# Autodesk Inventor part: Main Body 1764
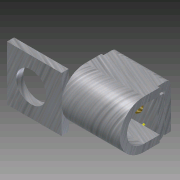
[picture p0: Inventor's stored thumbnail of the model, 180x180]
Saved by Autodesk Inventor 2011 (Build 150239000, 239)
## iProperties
Created: 2008-01
Part Number: Main Body 1764
Document SubType Name: Modeling
Designer: rlindsay
Density: 1 g/cm^3
Author: rlindsay
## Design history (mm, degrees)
sketch "Sketch1"
  geometry: L1 (-12.629, -4.841)-(0.071, -4.841); L2 (0.071, -4.841)-(0.071, -17.541); L3 (0.071, -17.541)-(-12.629, -17.541); L4 (-12.629, -17.541)-(-12.629, -4.841); C1 r 3.493 at (-6.978, -11.191)
  constraints: 8 end point, 2 parallel, 1 centre point, 1 horizontal, 1 perpendicular
  dimensions: "d0" = 6.985 diameter of C1; "d1" = 12.7 distance between parallel lines of L3 L1; "d2" = 6.35 distance from line of L3 C1.centre (= 0.5 x d1); "d3" = 12.7 distance of L1.start L1.end; "d5" = 7.0485 distance from line of L2 C1.centre (computed from d0)
extrude "Extrusion1" new body sketch "Sketch1" distance "d6" = 1.651; taper "d7" = 0 deg
sketch "Sketch2"
  geometry: L1 (-1.651, 12.7)-(-1.651, 0) reference; L2 (0, 0)-(-1.651, 0) reference; L3 (0, 12.7)-(0, 0) reference; L4 (0, 12.7)-(-1.651, 12.7) reference; L5 (10.795, 1.27)-(10.795, 10.668); L6 (9.525, 11.938)-(3.937, 11.938); L7 (9.271, 1.27)-(9.271, 10.287); L8 (9.271, 10.287)-(3.937, 10.287); L9 (3.937, 2.413)-(7.62, 2.413); L10 (7.62, 2.413)-(7.62, 9.779); L11 (7.62, 9.779)-(9.144, 9.779); L12 (9.144, 9.779)-(9.144, 2.032); L13 (3.937, 0.762)-(7.874, 0.762); L14 (9.271, 1.27)-(10.795, 1.27); A1 r 5.588 centre (3.937, 6.35) between (3.937, 11.938) and (3.937, 0.762); A2 r 3.937 centre (3.937, 6.35) between (3.937, 10.287) and (3.937, 2.413); A3 r 1.27 centre (9.525, 10.668) between (10.795, 10.668) and (9.525, 11.938); A4 r 1.27 centre (7.874, 2.032) between (7.874, 0.762) and (9.144, 2.032)
  constraints: 20 end point, 9 point on circle, 6 perpendicular, 5 parallel, 4 centre point, 2 horizontal, 2 tangent, 1 coincident
  dimensions: "d8" = 11.176 diameter of A1; "d9" = 6.35 distance from line of L4 A1.centre; "d11" = 0 horizontal distance of L8.end A1.centre; "d12" = 0 horizontal distance of A2.centre L6.end; "d13" = 0 horizontal distance of A1.centre L9.start; "d14" = 0 horizontal distance of A1.centre L13.start; "d15" = 1.524 distance between parallel lines of L5 L7; "d16" = 1.524 distance between parallel lines of L10 L12; "d17" = 0.508 distance between parallel lines of L8 L11; "d18" = 0.508 distance between parallel lines of L13 L14; "d19" = 0.127 distance between parallel lines of L12 L7; "d20" = 1.27 radius of A3; "d21" = 1.27 distance from line of L6 A3.centre (= d20); "d22" = 1.27 distance from line of L5 A3.centre (= d20); "d23" = 1.27 radius of A4 (= d20); "d24" = 1.27 distance from line of L13 A4.centre (= d20); "d25" = 1.27 distance from line of L12 A4.centre (= d20); "d26" = 7.62 distance between parallel lines of L3 L10
extrude "Extrusion2" join sketch "Sketch2" distance "d27" = 13.589; taper "d28" = 0 deg
sketch "Sketch3"
  geometry: L1 (-7.62, -0.713)-(-11.884, -0.713); L2 (-11.884, -0.713)-(-11.884, 13.854); L3 (-11.884, 13.854)-(-7.62, 13.854); L4 (-7.62, 13.854)-(-7.62, -0.713); L5 (-7.62, 9.779)-(-7.62, 2.413) reference
  constraints: 8 end point, 2 parallel, 1 horizontal, 1 perpendicular
  dimensions: "d29" = 0 distance between parallel lines of L4 L5
extrude "Extrusion3" cut sketch "Sketch3" distance "d30" = 0.508; taper "d31" = 0 deg
sketch "Sketch4"
  geometry: L1 (7.62, 2.413)-(7.62, 9.779) reference; L2 (7.62, -4.452)-(11.156, -4.452); L3 (11.156, -4.452)-(11.156, 13.283); L4 (11.156, 13.283)-(7.62, 13.283); L5 (7.62, 13.283)-(7.62, -4.452)
  constraints: 8 end point, 2 parallel, 1 horizontal, 1 perpendicular
  dimensions: "d32" = 0 distance between parallel lines of L1 L5
extrude "Extrusion4" cut sketch "Sketch4" distance "d33" = 0.508; taper "d34" = 0 deg
sketch "Sketch5"
  geometry: L1 (0, 10.668)-(-12.573, 10.668) reference; L2 (0, -0.508)-(-12.573, -0.508) reference; C1 r 2.54 at (-6.748, 5.08)
  constraints: 1 centre point
  dimensions: "d35" = 5.588 distance from line of L1 C1.centre; "d36" = 5.588 distance from line of L2 C1.centre (derived); "d37" = 5.08 diameter of C1
extrude "Extrusion5" cut sketch "Sketch5" distance "d38" = 6.35; taper "d39" = 0 deg
thread "Thread1" dims "d40" = 25.4, "d41" = 0
thread "Thread2" dims "d42" = 25.4, "d43" = 0
sketch "Sketch6"
  geometry: A1 r 3.937 centre (3.937, 6.35) between (3.937, 10.287) and (3.937, 2.413) reference
node "+"
body "Solid1"
